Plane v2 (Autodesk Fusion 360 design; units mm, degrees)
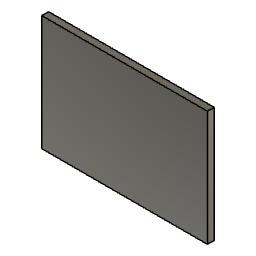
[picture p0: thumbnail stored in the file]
sketch "Sketch1" plane through (0, 0, 0) normal (0, 1, 0) x axis (1, 0, 0)
  line L1 (244.37, 0) -> (0, 0)
  line L2 (244.37, -170) -> (244.37, 0)
  line L3 (0, -170) -> (244.37, -170)
  line L4 (0, 0) -> (0, -170)
  point P1 (0, 0)
  point P2 (0, 0)
  point P3 (244.37, 0)
  horizontal L1
  vertical L2
  horizontal L3
  vertical L4
  coincident P1 P2
  dimension "d1" distance P2 P3 = 244.37
extrude "Extrude1" new body sketch "Sketch1" along normal blind 10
